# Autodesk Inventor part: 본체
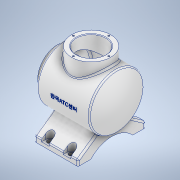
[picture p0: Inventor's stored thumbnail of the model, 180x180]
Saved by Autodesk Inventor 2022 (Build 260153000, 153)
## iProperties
Created: 2023-04
Part Number: 본체
Material: 알루미늄 6061
Document SubType Name: Modeling
Designer: Admin
Mass: 1295.51 g
Surface Area: 1065.12 cm^2
Volume: 479.817 cm^3
Density: 2.7 g/cm^3
Appearance: 알루미늄 - 평지
Author: Admin
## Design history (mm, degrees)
sketch "스케치1"
  geometry: L1 (-84.575, 0)-(87.453, 0) reference; L2 (0, -10.134)-(0, 60.805) reference; L3 (-60, 0)-(-48, 0); L4 (-48, 0)-(-48, 36); L5 (-48, 36)-(-60, 36); L6 (-60, 36)-(-60, 0); L7 (-48, 0)-(-31.477, 0); L8 (-31.477, 0)-(10.095, 0); L9 (10.095, 0)-(13.571, 0); L10 (-48, 0)-(48.336, 0); L11 (48.336, 0)-(48.336, 50); L12 (48.336, 50)-(-48, 50); L13 (-48, 50)-(-48, 0); L14 (48.336, 0)-(60, 0); A1 r 113 centre (-53, 0) between (60, 0) and (48.336, 50); 3 further points
  constraints: 24 end point, 5 horizontal, 4 parallel, 3 point on line, 2 perpendicular, 2 point on circle, 1 centre point, 1 symmetric about line
  dimensions: "d0" = 72 diameter of L5 L1; "d6" = 50 distance of L10.end L11.end; "d8" = 108 distance edge to line of A1 L13; "d9" = 120 dimension on A1 L6; "d10" = 226 diameter of A1
revolve "회전1" sketch "스케치1" stored, may be unused: angle "d11" = 90 deg
sketch "스케치3"
  geometry: L1 (-93.622, 0)-(90.395, 0); L2 (-60, -36)-(-60, 36) reference; L3 (-60, 0)-(-41, 0); L4 (-41, 0)-(-41, 27); L5 (-41, 27)-(-60, 27); L6 (-60, 27)-(-60, 0); L7 (-41, 0)-(43.887, 0); L8 (43.887, 0)-(43.887, 43); L9 (43.887, 43)-(-41, 43); L10 (-41, 43)-(-41, 0); L11 (43.887, 0)-(53, 0); L12 (53, 0)-(60, 0); A1 r 106 centre (-53, 0) between (53, 0) and (43.887, 43); A2 r 113 centre (-53, 0) between (48.336, -50) and (48.336, 50) reference; 3 further points
  constraints: 22 end point, 4 parallel, 3 horizontal, 3 point on circle, 3 point on line, 2 perpendicular, 1 centre point, 1 midpoint
  dimensions: "d12" = 212 diameter of A1; "d13" = 54 diameter of L5 L1; "d14" = 86 diameter of L9 L1; "d15" = 19 distance of L4.end L5.end; "d17" = 7 distance of L11.end L12.end
revolve "회전2" sketch "스케치3" stored, may be unused: angle "d18" = 90 deg
node "작업 평면1"
sketch "스케치4"
  geometry: L1 (60, 36)-(60, -36) reference; L2 (79.6, 0)-(-57.6, 0) reference; C1 r 36 at (-2, 0); 1 further point
  constraints: 1 centre point, 1 point on line
  dimensions: "d20" = 62 distance from line of C1.centre L1; "d21" = 72 diameter of C1
extrude "돌출1" join sketch "스케치4" stored distance "d22" = 10; taper "d23" = 0 deg
sketch "스케치5"
  geometry: C1 r 36 at (0, 0) reference; C2 r 27 at (0, 0); 1 further point
  constraints: 1 centre point, 1 coincident
  dimensions: "d24" = 54 diameter of C2
extrude "돌출2" cut sketch "스케치5" stored distance "d25" = 10; taper "d26" = 0 deg
sketch "스케치7" dims "d63" = 65
  geometry: 3 further points
  constraints: 2 vertical alignment, 1 coincident, 2 other
hole "구멍1" sketch "스케치7" at (0, 32.5) diameter "d64" = 3.242; stored, may be unused: countersink angle "d68" = 90 deg, drill point angle "d70" = 118 deg; dims "d65" = 8, "d66" = 4, "d67" = 2, "d69" = 10
sketch "스케치8" dims "d74" = 65
  geometry: C1 r 27 at (0, 0) reference; 3 further points
  constraints: 2 horizontal alignment, 1 coincident, 2 other
hole "구멍2" sketch "스케치8" at (32.5, 0) diameter "d75" = 3.242; stored, may be unused: countersink angle "d79" = 90 deg, drill point angle "d81" = 118 deg; dims "d76" = 8, "d77" = 4, "d78" = 2, "d80" = 10
node "작업 평면2"
sketch "스케치12"
  geometry: L1 (27, 51.324)-(27, 80.958); L2 (13, 52.982)-(13, 80.958); L3 (27, 80.958)-(13, 80.958); C1 r 4.5 at (20, 53) reference; C2 r 7 at (20, 53); 3 further points
  constraints: 6 end point, 2 tangent, 2 vertical, 1 centre point, 1 coincident, 1 perpendicular
  dimensions: "d93" = 14 diameter of C2
extrude "돌출5" cut sketch "스케치12" distance "d94" = 19.5; taper "d95" = 0 deg
chamfer "모따기1" distance "d96" = 1; stored, may be unused: second distance "d97" = 2, angle "d98" = 45 deg
node "작업 평면6"
fillet "모깎기2" dims "d134" = 3
fillet "모깎기3" dims "d135" = 3
fillet "모깎기4" dims "d136" = 3
sketch "스케치21"
  geometry: 1 further point
node "작업 평면7"
sketch "스케치22"
  geometry: L1 (-60, -36)-(-60, 36) reference; L2 (-72.4, 0)-(14.4, 0) reference; 2 further points
  constraints: 1 point on line, 1 other
  dimensions: "d138" = 62 distance from line of L1 point (2, 0)
feature "엠보싱1" sketch "스케치22" dims "d12" = 212, "d13" = 54, "d14" = 86, "d15" = 19, "d17" = 7, "d139" = 0.5, "d140" = 0
node "작업 평면8"
sketch "스케치23"
  geometry: L1 (-102.4, 0)-(75.4, 0) reference; L2 (0, -72.4)-(0, 84.4) reference; L3 (-77, 0)-(-77, 62); L4 (-77, 62)-(-67, 62); L5 (-67, 62)-(-42.278, 26.694); L6 (-77, 0)-(-50, 0); A1 r 50 centre (0, 0) between (-42.278, 26.694) and (-50, 0); 2 further points
  constraints: 8 end point, 2 point on circle, 2 point on line, 1 centre point, 1 coincident, 1 perpendicular, 1 vertical, 2 other
  dimensions: "d142" = 77 distance between parallel lines of L3 L2; "d143" = 10 distance of L3.end L4.end; "d144" = 55 deg angle of L5 L4; "d145" = 62 distance between parallel lines of L1 L4
extrude "돌출11" join sketch "스케치23" distance "d146" = 80; taper "d147" = 0 deg
sketch "스케치24"
  geometry: L1 (62, -77)-(0, -77) reference; L2 (0, -177.4)-(0, 105.4) reference; L3 (38.5, -77)-(38.5, -54.572); 2 further points
  constraints: 2 end point, 2 point on line, 1 perpendicular, 3 other
  dimensions: "d151" = 17 dimension on L1; "d170" = 38.5 distance from line of L3 L1.end
extrude "돌출12" cut sketch "스케치24" extent not by distance; stored distance "d152" = 0; taper "d153" = 0 deg
sketch "스케치25"
  geometry: L1 (80, 0)-(80, -23.5) reference; L2 (0, 0)-(80, 0) reference; L3 (0, 0)-(0, -23.5) reference; C1 r 4.5 at (20, -8); C2 r 4.5 at (60, -8); 1 further point
  constraints: 2 centre point
  dimensions: "d154" = 20 distance from line of L1 C2.centre; "d155" = 8 distance from line of L2 C2.centre; "d156" = 8 distance from line of L2 C1.centre; "d157" = 20 distance from line of C1.centre L3; "d158" = 9 diameter of C1; "d159" = 9 diameter of C2
extrude "돌출13" cut sketch "스케치25" distance "d160" = 6; taper "d161" = 0 deg
sketch "스케치26"
  geometry: C1 r 4.5 at (0, 0) reference; C2 r 4.5 at (40, 0) reference; C3 r 7 at (0, 0); C4 r 7 at (40, 0); 1 further point
  constraints: 2 centre point, 2 coincident
  dimensions: "d162" = 14 diameter of C4; "d163" = 14 diameter of C3
extrude "돌출14" cut sketch "스케치26" distance "d164" = 15; taper "d165" = 0 deg
sketch "스케치27" dims "d166" = 14
  geometry: L1 (-7, 0.601)-(-7, -16.919); L2 (-7, -16.919)-(7, -16.919); L3 (7, -16.919)-(7, 0); C1 r 4.5 at (0, 0) reference; 3 further points
  constraints: 6 end point, 4 vertical, 1 coincident, 1 perpendicular, 3 other
extrude "돌출15" cut sketch "스케치27" distance "d167" = 15; taper "d168" = 0 deg
fillet "모깎기5" dims "d169" = 3
node "솔리드1"
pattern_circular "원형 패턴1" dims angle "d72" = 360 deg
pattern_circular "원형 패턴2" dims angle "d83" = 360 deg
mirror "미러2"
mirror "미러3"
mirror "미러7"
mirror "미러8"
mirror "미러9"
node "투영된 루프4"
node "투영된 루프5"
feature "A9D066F2-1C7D-4E18-AEED-F7BC21143FA4" dims "d64" = 3.242, "d65" = 8, "d66" = 4, "d67" = 2, "d68" = 90 deg, "d69" = 10, "d70" = 118 deg
other parameters: "d19" = 65, "d39" = 77, "d43" = 17, "d49" = 17, "d92" = -51.75, "d137" = 121.75
